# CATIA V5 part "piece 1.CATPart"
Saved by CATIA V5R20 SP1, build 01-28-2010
Part number: piece 1
Bounding box of the stored display mesh (mm): x -19.998 to 419.998, y -19.998 to 319.998, z 0 to 10
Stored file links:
  D:\Dropbox\IAO_2011\MMS_GR1\jdubreuilr\jdubreuilr\jdubreuilr\piece 1.CATPart
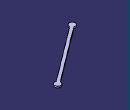
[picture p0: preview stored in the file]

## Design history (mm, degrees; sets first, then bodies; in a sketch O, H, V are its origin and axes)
Set1
  Point1 "Point B": (0, 0, 0)
  Point2 "Point A": (400, 300, 0)
  Line1: type Normal, RefPoint Point2, RefSkin end face of Pad1, Start 0, End 20
  Line2: type Normal, RefPoint Point1, RefSkin end face of Pad1, Start 0, End 20
Body1 (main body)
  Sketch1 on xy-plane, origin (0, 0, 0), H (1, 0, 0), V (0, 1, 0)
    line L1 (380.1436, 297.6077) -> (7.8564, 18.3923)
    point P1 (380.1436, 297.6077)
    point P2 (7.8564, 18.3923)
    line L2 (392.1436, 281.6077) -> (19.8564, 2.3923)
    point P3 (19.8564, 2.3923)
    point P4 (392.1436, 281.6077)
    arc A1 centre (400, 300) radius 20 from (392.1436, 281.6077) to (380.1436, 297.6077) ccw
    point P5 (392.1436, 281.6077)
    point P6 (380.1436, 297.6077)
    arc A2 centre (0, 0) radius 20 from (7.8564, 18.3923) to (19.8564, 2.3923) ccw
    point P7 (7.8564, 18.3923)
    point P8 (19.8564, 2.3923)
    radius A1 = 20
    radius A2 = 20
    coincidence: P5 L2, P6 L1, P4 P5, P1 P6, P7 L1, P8 L2, P2 P7, P8 P3
  Pad1: profile Sketch1, direction (0, 0, 1), length 10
